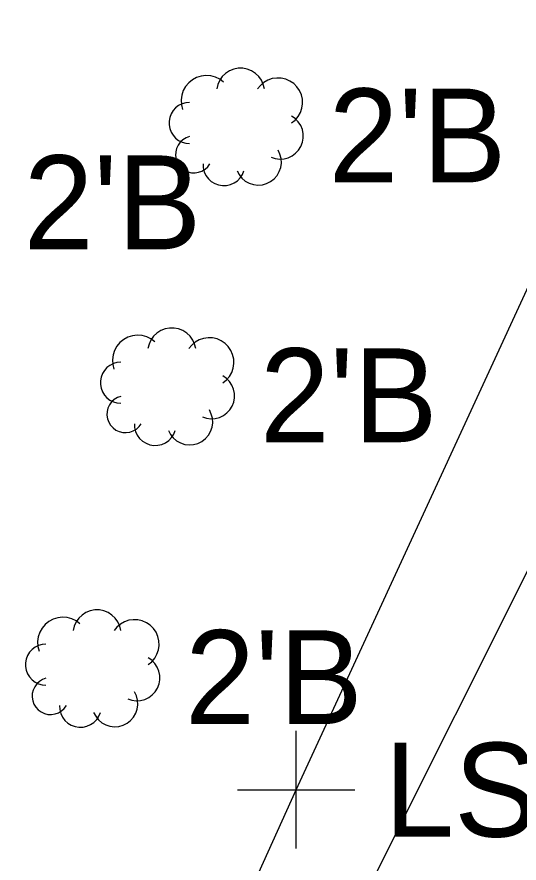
# Model space of a CAD drawing. Extents: x 1363693 to 1365209, y 422201 to 424153.
# Drawn here: x 1364154.64 to 1364163.19, y 422936.96 to 422951.37 of the extents above; entities that cross this region are included whole.
import ezdxf

# ---------------------------------------------------------------- set-up
doc = ezdxf.new("R2010")
doc.units = 0
for name, color, linetype in [('SV_X_Random_Point', 7, 'Continuous'), ('UT_X_FO', 7, 'Continuous'), ('VG_X_Cells', 7, 'Continuous'), ('VG_X_Flower_Bed', 7, 'Continuous'), ('VG_X_Text', 7, 'Continuous')]:
    doc.layers.add(name, color=color, linetype=linetype)

msp = doc.modelspace()

# ---------------------------------------------------------------- linework, layer by layer
at = {"layer": 'SV_X_Random_Point'}
for p, q in [((1364159.397, 422937.209), (1364159.397, 422939.209)), ((1364158.397, 422938.209), (1364160.397, 422938.209))]:
    msp.add_line(p, q, dxfattribs=at)
at = {"layer": 'UT_X_FO'}
msp.add_lwpolyline([(1364198.41, 423083.145), (1364202.916, 423079.215), (1364206.614, 423072.625), (1364206.927, 423065.384), (1364205.607, 423052.889), (1364202.652, 423033.176), (1364193.585, 423006.537), (1364182.955, 422981.103), (1364130.325, 422876.058), (1364040.63, 422724.214)], dxfattribs=at)
at = {"layer": 'VG_X_Cells'}
for points in [[(1364158.855, 422950.145), (1364158.836, 422950.22), (1364158.804, 422950.291), (1364158.759, 422950.355), (1364158.702, 422950.409), (1364158.637, 422950.451), (1364158.564, 422950.48), (1364158.488, 422950.495), (1364158.409, 422950.495), (1364158.333, 422950.48), (1364158.26, 422950.451), (1364158.195, 422950.409), (1364158.138, 422950.355), (1364158.093, 422950.291), (1364158.06, 422950.22), (1364158.042, 422950.145)], [(1364158.158, 422950.261), (1364158.093, 422950.31), (1364158.02, 422950.345), (1364157.941, 422950.367), (1364157.859, 422950.373), (1364157.778, 422950.363), (1364157.7, 422950.339), (1364157.629, 422950.3), (1364157.565, 422950.249), (1364157.513, 422950.186), (1364157.473, 422950.115), (1364157.447, 422950.038), (1364157.437, 422949.957), (1364157.442, 422949.875), (1364157.462, 422949.796)], [(1364159.319, 422949.564), (1364159.38, 422949.613), (1364159.43, 422949.672), (1364159.469, 422949.74), (1364159.494, 422949.814), (1364159.505, 422949.89), (1364159.502, 422949.968), (1364159.484, 422950.044), (1364159.453, 422950.115), (1364159.409, 422950.18), (1364159.354, 422950.235), (1364159.29, 422950.278), (1364159.219, 422950.31), (1364159.143, 422950.327), (1364159.065, 422950.33), (1364158.988, 422950.319), (1364158.915, 422950.294), (1364158.847, 422950.255), (1364158.788, 422950.205), (1364158.739, 422950.145)], [(1364157.578, 422949.912), (1364157.514, 422949.906), (1364157.452, 422949.889), (1364157.394, 422949.86), (1364157.343, 422949.821), (1364157.3, 422949.774), (1364157.266, 422949.719), (1364157.243, 422949.659), (1364157.231, 422949.596), (1364157.231, 422949.532), (1364157.243, 422949.469), (1364157.266, 422949.409), (1364157.3, 422949.354), (1364157.343, 422949.307), (1364157.394, 422949.268), (1364157.452, 422949.239), (1364157.514, 422949.222), (1364157.578, 422949.216)], [(1364158.971, 422948.983), (1364159.041, 422948.96), (1364159.115, 422948.95), (1364159.189, 422948.955), (1364159.261, 422948.973), (1364159.328, 422949.005), (1364159.387, 422949.049), (1364159.438, 422949.103), (1364159.477, 422949.166), (1364159.504, 422949.235), (1364159.517, 422949.308), (1364159.516, 422949.382), (1364159.501, 422949.455), (1364159.473, 422949.523), (1364159.432, 422949.585), (1364159.38, 422949.638), (1364159.319, 422949.68)], [(1364157.578, 422949.332), (1364157.52, 422949.311), (1364157.467, 422949.279), (1364157.422, 422949.237), (1364157.386, 422949.187), (1364157.36, 422949.132), (1364157.345, 422949.072), (1364157.343, 422949.011), (1364157.352, 422948.95), (1364157.373, 422948.892), (1364157.405, 422948.84), (1364157.447, 422948.794), (1364157.496, 422948.758), (1364157.552, 422948.732), (1364157.612, 422948.717), (1364157.673, 422948.714), (1364157.734, 422948.724), (1364157.792, 422948.745), (1364157.844, 422948.776), (1364157.89, 422948.818), (1364157.926, 422948.867)], [(1364158.39, 422948.751), (1364158.425, 422948.684), (1364158.473, 422948.624), (1364158.53, 422948.575), (1364158.597, 422948.538), (1364158.669, 422948.515), (1364158.744, 422948.506), (1364158.82, 422948.511), (1364158.893, 422948.532), (1364158.961, 422948.565), (1364159.021, 422948.612), (1364159.071, 422948.669), (1364159.109, 422948.735), (1364159.134, 422948.807), (1364159.144, 422948.882), (1364159.139, 422948.958), (1364159.12, 422949.031), (1364159.087, 422949.1)], [(1364157.81, 422948.867), (1364157.814, 422948.799), (1364157.831, 422948.733), (1364157.86, 422948.671), (1364157.9, 422948.615), (1364157.951, 422948.569), (1364158.009, 422948.533), (1364158.073, 422948.509), (1364158.141, 422948.498), (1364158.21, 422948.5), (1364158.276, 422948.515), (1364158.339, 422948.542), (1364158.395, 422948.581), (1364158.443, 422948.63), (1364158.481, 422948.688), (1364158.507, 422948.751)], [(1364157.685, 422945.721), (1364157.666, 422945.796), (1364157.634, 422945.867), (1364157.589, 422945.931), (1364157.532, 422945.985), (1364157.467, 422946.027), (1364157.394, 422946.056), (1364157.318, 422946.071), (1364157.239, 422946.071), (1364157.163, 422946.056), (1364157.09, 422946.027), (1364157.025, 422945.985), (1364156.968, 422945.931), (1364156.923, 422945.867), (1364156.89, 422945.796), (1364156.872, 422945.721)], [(1364156.988, 422945.837), (1364156.923, 422945.886), (1364156.85, 422945.921), (1364156.771, 422945.943), (1364156.689, 422945.949), (1364156.608, 422945.939), (1364156.53, 422945.915), (1364156.459, 422945.876), (1364156.395, 422945.825), (1364156.343, 422945.762), (1364156.303, 422945.691), (1364156.277, 422945.614), (1364156.267, 422945.533), (1364156.272, 422945.451), (1364156.292, 422945.372)], [(1364158.149, 422945.14), (1364158.21, 422945.189), (1364158.26, 422945.248), (1364158.299, 422945.316), (1364158.324, 422945.39), (1364158.335, 422945.466), (1364158.332, 422945.544), (1364158.314, 422945.62), (1364158.283, 422945.691), (1364158.239, 422945.756), (1364158.184, 422945.811), (1364158.12, 422945.854), (1364158.049, 422945.886), (1364157.973, 422945.903), (1364157.895, 422945.906), (1364157.818, 422945.895), (1364157.745, 422945.87), (1364157.677, 422945.831), (1364157.618, 422945.781), (1364157.569, 422945.721)], [(1364156.408, 422945.488), (1364156.344, 422945.482), (1364156.282, 422945.465), (1364156.224, 422945.436), (1364156.173, 422945.397), (1364156.13, 422945.35), (1364156.096, 422945.295), (1364156.073, 422945.235), (1364156.061, 422945.172), (1364156.061, 422945.108), (1364156.073, 422945.045), (1364156.096, 422944.985), (1364156.13, 422944.93), (1364156.173, 422944.883), (1364156.224, 422944.844), (1364156.282, 422944.815), (1364156.344, 422944.798), (1364156.408, 422944.792)], [(1364157.801, 422944.559), (1364157.871, 422944.536), (1364157.945, 422944.526), (1364158.019, 422944.531), (1364158.091, 422944.549), (1364158.158, 422944.581), (1364158.217, 422944.625), (1364158.268, 422944.679), (1364158.307, 422944.742), (1364158.334, 422944.811), (1364158.347, 422944.884), (1364158.346, 422944.958), (1364158.331, 422945.031), (1364158.303, 422945.099), (1364158.262, 422945.161), (1364158.21, 422945.214), (1364158.149, 422945.256)], [(1364156.408, 422944.908), (1364156.35, 422944.887), (1364156.297, 422944.855), (1364156.252, 422944.813), (1364156.216, 422944.763), (1364156.19, 422944.708), (1364156.175, 422944.648), (1364156.173, 422944.587), (1364156.182, 422944.526), (1364156.203, 422944.468), (1364156.235, 422944.416), (1364156.277, 422944.37), (1364156.326, 422944.334), (1364156.382, 422944.308), (1364156.442, 422944.293), (1364156.503, 422944.29), (1364156.564, 422944.3), (1364156.622, 422944.321), (1364156.674, 422944.352), (1364156.72, 422944.394), (1364156.756, 422944.443)], [(1364157.22, 422944.327), (1364157.255, 422944.26), (1364157.303, 422944.2), (1364157.36, 422944.151), (1364157.427, 422944.114), (1364157.499, 422944.091), (1364157.574, 422944.082), (1364157.65, 422944.087), (1364157.723, 422944.108), (1364157.791, 422944.141), (1364157.851, 422944.188), (1364157.901, 422944.245), (1364157.939, 422944.311), (1364157.964, 422944.383), (1364157.974, 422944.458), (1364157.969, 422944.534), (1364157.95, 422944.607), (1364157.917, 422944.676)], [(1364156.64, 422944.443), (1364156.644, 422944.375), (1364156.661, 422944.309), (1364156.69, 422944.247), (1364156.73, 422944.191), (1364156.781, 422944.145), (1364156.839, 422944.109), (1364156.903, 422944.085), (1364156.971, 422944.074), (1364157.04, 422944.076), (1364157.106, 422944.091), (1364157.169, 422944.118), (1364157.225, 422944.157), (1364157.273, 422944.206), (1364157.311, 422944.264), (1364157.337, 422944.327)], [(1364156.411, 422940.92), (1364156.392, 422940.995), (1364156.36, 422941.066), (1364156.315, 422941.13), (1364156.258, 422941.184), (1364156.193, 422941.226), (1364156.12, 422941.255), (1364156.044, 422941.27), (1364155.965, 422941.27), (1364155.889, 422941.255), (1364155.816, 422941.226), (1364155.751, 422941.184), (1364155.694, 422941.13), (1364155.649, 422941.066), (1364155.616, 422940.995), (1364155.598, 422940.92)], [(1364155.714, 422941.036), (1364155.649, 422941.085), (1364155.576, 422941.12), (1364155.497, 422941.142), (1364155.415, 422941.148), (1364155.334, 422941.138), (1364155.256, 422941.114), (1364155.185, 422941.075), (1364155.121, 422941.024), (1364155.069, 422940.961), (1364155.029, 422940.89), (1364155.003, 422940.813), (1364154.993, 422940.732), (1364154.998, 422940.65), (1364155.018, 422940.571)], [(1364156.875, 422940.339), (1364156.936, 422940.388), (1364156.986, 422940.447), (1364157.025, 422940.515), (1364157.05, 422940.589), (1364157.061, 422940.665), (1364157.058, 422940.743), (1364157.04, 422940.819), (1364157.009, 422940.89), (1364156.965, 422940.955), (1364156.91, 422941.01), (1364156.846, 422941.053), (1364156.775, 422941.085), (1364156.699, 422941.102), (1364156.621, 422941.105), (1364156.544, 422941.094), (1364156.471, 422941.069), (1364156.403, 422941.03), (1364156.344, 422940.98), (1364156.295, 422940.92)], [(1364155.134, 422940.687), (1364155.07, 422940.681), (1364155.008, 422940.664), (1364154.95, 422940.635), (1364154.899, 422940.596), (1364154.856, 422940.549), (1364154.822, 422940.494), (1364154.799, 422940.434), (1364154.787, 422940.371), (1364154.787, 422940.307), (1364154.799, 422940.244), (1364154.822, 422940.184), (1364154.856, 422940.129), (1364154.899, 422940.082), (1364154.95, 422940.043), (1364155.008, 422940.014), (1364155.07, 422939.997), (1364155.134, 422939.991)], [(1364156.527, 422939.758), (1364156.597, 422939.735), (1364156.671, 422939.725), (1364156.745, 422939.73), (1364156.817, 422939.748), (1364156.884, 422939.78), (1364156.943, 422939.824), (1364156.994, 422939.878), (1364157.033, 422939.941), (1364157.06, 422940.01), (1364157.073, 422940.083), (1364157.072, 422940.157), (1364157.057, 422940.23), (1364157.029, 422940.298), (1364156.988, 422940.36), (1364156.936, 422940.413), (1364156.875, 422940.455)], [(1364155.134, 422940.107), (1364155.076, 422940.086), (1364155.023, 422940.054), (1364154.978, 422940.012), (1364154.942, 422939.962), (1364154.916, 422939.907), (1364154.901, 422939.847), (1364154.899, 422939.786), (1364154.908, 422939.725), (1364154.929, 422939.667), (1364154.961, 422939.615), (1364155.003, 422939.569), (1364155.052, 422939.533), (1364155.108, 422939.507), (1364155.168, 422939.492), (1364155.229, 422939.489), (1364155.29, 422939.499), (1364155.348, 422939.52), (1364155.4, 422939.551), (1364155.446, 422939.593), (1364155.482, 422939.642)], [(1364155.946, 422939.526), (1364155.981, 422939.459), (1364156.029, 422939.399), (1364156.086, 422939.35), (1364156.153, 422939.313), (1364156.225, 422939.29), (1364156.3, 422939.281), (1364156.376, 422939.286), (1364156.449, 422939.307), (1364156.517, 422939.34), (1364156.577, 422939.387), (1364156.627, 422939.444), (1364156.665, 422939.51), (1364156.69, 422939.582), (1364156.7, 422939.657), (1364156.695, 422939.733), (1364156.676, 422939.806), (1364156.643, 422939.875)], [(1364155.366, 422939.642), (1364155.37, 422939.574), (1364155.387, 422939.508), (1364155.416, 422939.446), (1364155.456, 422939.39), (1364155.507, 422939.344), (1364155.565, 422939.308), (1364155.629, 422939.284), (1364155.697, 422939.273), (1364155.766, 422939.275), (1364155.832, 422939.29), (1364155.895, 422939.317), (1364155.951, 422939.356), (1364155.999, 422939.405), (1364156.037, 422939.463), (1364156.063, 422939.526)]]:
    msp.add_lwpolyline(points, dxfattribs=at)
at = {"layer": 'VG_X_Flower_Bed'}
for p, q in [((1364159.397, 422938.209), (1364169.366, 422959.835)), ((1364150.21, 422917.879), (1364159.397, 422938.209))]:
    msp.add_line(p, q, dxfattribs=at)

# ---------------------------------------------------------------- texts
at = {"layer": 'SV_X_Random_Point'}
msp.add_text('LS C', height=1.6, dxfattribs=at).set_placement((1364160.897, 422937.409))
at = {"layer": 'VG_X_Text'}
for p in [(1364159.948, 422948.551), (1364154.754, 422947.413), (1364158.778, 422944.127), (1364157.504, 422939.326)]:
    msp.add_text("2'B", height=1.6, dxfattribs=at).set_placement(p)

doc.saveas('drawing.dxf')
